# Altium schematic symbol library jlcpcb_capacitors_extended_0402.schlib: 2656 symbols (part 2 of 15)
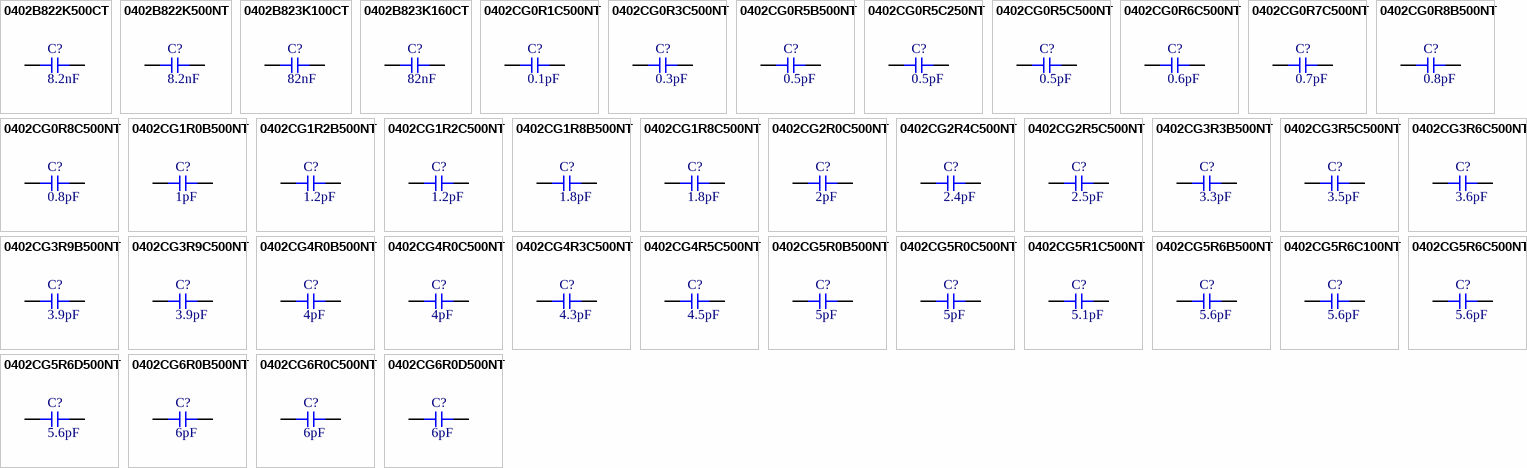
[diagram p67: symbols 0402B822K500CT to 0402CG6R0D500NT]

## 0402CG2R5C500NT
designator C?  Capacitance: 2.5pF  (hidden comment: *)
Capacitor, Ceramic (MLCC), 2.5pF, ±0.25pF, 50V, C0G, ±0.25pF, SMD 0402; Manufacturer: FH(Guangdong Fenghua Advanced Tech); Manufacturer Part Number: 0402CG2R5C500NT
footprint CAP-0402 (0402 (1005M) Capacitor)
pins: 1, 2

## 0402CG3R3B500NT
designator C?  Capacitance: 3.3pF  (hidden comment: *)
Capacitor, Ceramic (MLCC), 3.3pF, ±0.1pF, 50V, C0G, ±0.1pF, SMD 0402; Manufacturer: FH(Guangdong Fenghua Advanced Tech); Manufacturer Part Number: 0402CG3R3B500NT
footprint CAP-0402 (0402 (1005M) Capacitor)
pins: 1, 2

## 0402CG3R5C500NT
designator C?  Capacitance: 3.5pF  (hidden comment: *)
Capacitor, Ceramic (MLCC), 3.5pF, ±0.25pF, 50V, C0G, ±0.25pF, SMD 0402; Manufacturer: FH(Guangdong Fenghua Advanced Tech); Manufacturer Part Number: 0402CG3R5C500NT
footprint CAP-0402 (0402 (1005M) Capacitor)
pins: 1, 2

## 0402CG3R6C500NT
designator C?  Capacitance: 3.6pF  (hidden comment: *)
Capacitor, Ceramic (MLCC), 3.6pF, ±0.25pF, 50V, C0G, ±0.25pF, SMD 0402; Manufacturer: FH(Guangdong Fenghua Advanced Tech); Manufacturer Part Number: 0402CG3R6C500NT
footprint CAP-0402 (0402 (1005M) Capacitor)
pins: 1, 2

## 0402CG3R9B500NT
designator C?  Capacitance: 3.9pF  (hidden comment: *)
Capacitor, Ceramic (MLCC), 3.9pF, ±0.1pF, 50V, C0G, ±0.1pF, SMD 0402; Manufacturer: FH(Guangdong Fenghua Advanced Tech); Manufacturer Part Number: 0402CG3R9B500NT
footprint CAP-0402 (0402 (1005M) Capacitor)
pins: 1, 2

## 0402CG3R9C500NT
designator C?  Capacitance: 3.9pF  (hidden comment: *)
Capacitor, Ceramic (MLCC), 3.9pF, ±0.25pF, 50V, C0G, ±0.25pF, SMD 0402; Manufacturer: FH(Guangdong Fenghua Advanced Tech); Manufacturer Part Number: 0402CG3R9C500NT
footprint CAP-0402 (0402 (1005M) Capacitor)
pins: 1, 2

## 0402CG4R0B500NT
designator C?  Capacitance: 4pF  (hidden comment: *)
Capacitor, Ceramic (MLCC), 4pF, ±0.1pF, 50V, C0G, ±0.1pF, SMD 0402; Manufacturer: FH(Guangdong Fenghua Advanced Tech); Manufacturer Part Number: 0402CG4R0B500NT
footprint CAP-0402 (0402 (1005M) Capacitor)
pins: 1, 2

## 0402CG4R0C500NT
designator C?  Capacitance: 4pF  (hidden comment: *)
Capacitor, Ceramic (MLCC), 4pF, ±0.25pF, 50V, C0G, ±0.25pF, SMD 0402; Manufacturer: FH(Guangdong Fenghua Advanced Tech); Manufacturer Part Number: 0402CG4R0C500NT
footprint CAP-0402 (0402 (1005M) Capacitor)
pins: 1, 2

## 0402CG4R3C500NT
designator C?  Capacitance: 4.3pF  (hidden comment: *)
Capacitor, Ceramic (MLCC), 4.3pF, ±0.25pF, 50V, C0G, ±0.25pF, SMD 0402; Manufacturer: FH(Guangdong Fenghua Advanced Tech); Manufacturer Part Number: 0402CG4R3C500NT
footprint CAP-0402 (0402 (1005M) Capacitor)
pins: 1, 2

## 0402CG4R5C500NT
designator C?  Capacitance: 4.5pF  (hidden comment: *)
Capacitor, Ceramic (MLCC), 4.5pF, ±0.25pF, 50V, C0G, ±0.25pF, SMD 0402; Manufacturer: FH(Guangdong Fenghua Advanced Tech); Manufacturer Part Number: 0402CG4R5C500NT
footprint CAP-0402 (0402 (1005M) Capacitor)
pins: 1, 2

## 0402CG5R0B500NT
designator C?  Capacitance: 5pF  (hidden comment: *)
Capacitor, Ceramic (MLCC), 5pF, ±0.1pF, 50V, ±0.1pF, SMD 0402; Manufacturer: FH(Guangdong Fenghua Advanced Tech); Manufacturer Part Number: 0402CG5R0B500NT
footprint CAP-0402 (0402 (1005M) Capacitor)
pins: 1, 2

## 0402CG5R0C500NT
designator C?  Capacitance: 5pF  (hidden comment: *)
Capacitor, Ceramic (MLCC), 5pF, ±0.25pF, 50V, C0G, ±0.25pF, SMD 0402; Manufacturer: FH(Guangdong Fenghua Advanced Tech); Manufacturer Part Number: 0402CG5R0C500NT
footprint CAP-0402 (0402 (1005M) Capacitor)
pins: 1, 2

## 0402CG5R1C500NT
designator C?  Capacitance: 5.1pF  (hidden comment: *)
Capacitor, Ceramic (MLCC), 5.1pF, ±0.25pF, 50V, C0G, ±0.25pF, SMD 0402; Manufacturer: FH(Guangdong Fenghua Advanced Tech); Manufacturer Part Number: 0402CG5R1C500NT
footprint CAP-0402 (0402 (1005M) Capacitor)
pins: 1, 2

## 0402CG5R6B500NT
designator C?  Capacitance: 5.6pF  (hidden comment: *)
Capacitor, Ceramic (MLCC), 5.6pF, ±0.1pF, 50V, C0G, ±0.1pF, SMD 0402; Manufacturer: FH (Guangdong Fenghua Advanced Tech); Manufacturer Part Number: 0402CG5R6B500NT
footprint CAP-0402 (0402 (1005M) Capacitor)
pins: 1, 2

## 0402CG5R6C100NT
designator C?  Capacitance: 5.6pF  (hidden comment: *)
Capacitor, Ceramic (MLCC), 5.6pF, ±0.25pF, 10V, C0G, ±0.25pF, SMD 0402; Manufacturer: FH(Guangdong Fenghua Advanced Tech); Manufacturer Part Number: 0402CG5R6C100NT
footprint CAP-0402 (0402 (1005M) Capacitor)
pins: 1, 2

## 0402CG5R6C500NT
designator C?  Capacitance: 5.6pF  (hidden comment: *)
Capacitor, Ceramic (MLCC), 5.6pF, ±0.25pF, 50V, C0G, ±0.25pF, SMD 0402; Manufacturer: FH(Guangdong Fenghua Advanced Tech); Manufacturer Part Number: 0402CG5R6C500NT
footprint CAP-0402 (0402 (1005M) Capacitor)
pins: 1, 2

## 0402CG5R6D500NT
designator C?  Capacitance: 5.6pF  (hidden comment: *)
Capacitor, Ceramic (MLCC), 5.6pF, ±0.5pF, 50V, C0G, ±0.5pF, SMD 0402; Manufacturer: FH(Guangdong Fenghua Advanced Tech); Manufacturer Part Number: 0402CG5R6D500NT
footprint CAP-0402 (0402 (1005M) Capacitor)
pins: 1, 2

## 0402CG6R0B500NT
designator C?  Capacitance: 6pF  (hidden comment: *)
Capacitor, Ceramic (MLCC), 6pF, ±0.1pF, 50V, ±0.1pF, SMD 0402; Manufacturer: FH(Guangdong Fenghua Advanced Tech); Manufacturer Part Number: 0402CG6R0B500NT
footprint CAP-0402 (0402 (1005M) Capacitor)
pins: 1, 2

## 0402CG6R0C500NT
designator C?  Capacitance: 6pF  (hidden comment: *)
Capacitor, Ceramic (MLCC), 6pF, ±0.25pF, 50V, C0G, ±0.25pF, SMD 0402; Manufacturer: FH(Guangdong Fenghua Advanced Tech); Manufacturer Part Number: 0402CG6R0C500NT
footprint CAP-0402 (0402 (1005M) Capacitor)
pins: 1, 2

## 0402CG6R0D500NT
designator C?  Capacitance: 6pF  (hidden comment: *)
Capacitor, Ceramic (MLCC), 6pF, ±0.5pF, 50V, C0G, ±0.5pF, SMD 0402; Manufacturer: FH(Guangdong Fenghua Advanced Tech); Manufacturer Part Number: 0402CG6R0D500NT
footprint CAP-0402 (0402 (1005M) Capacitor)
pins: 1, 2

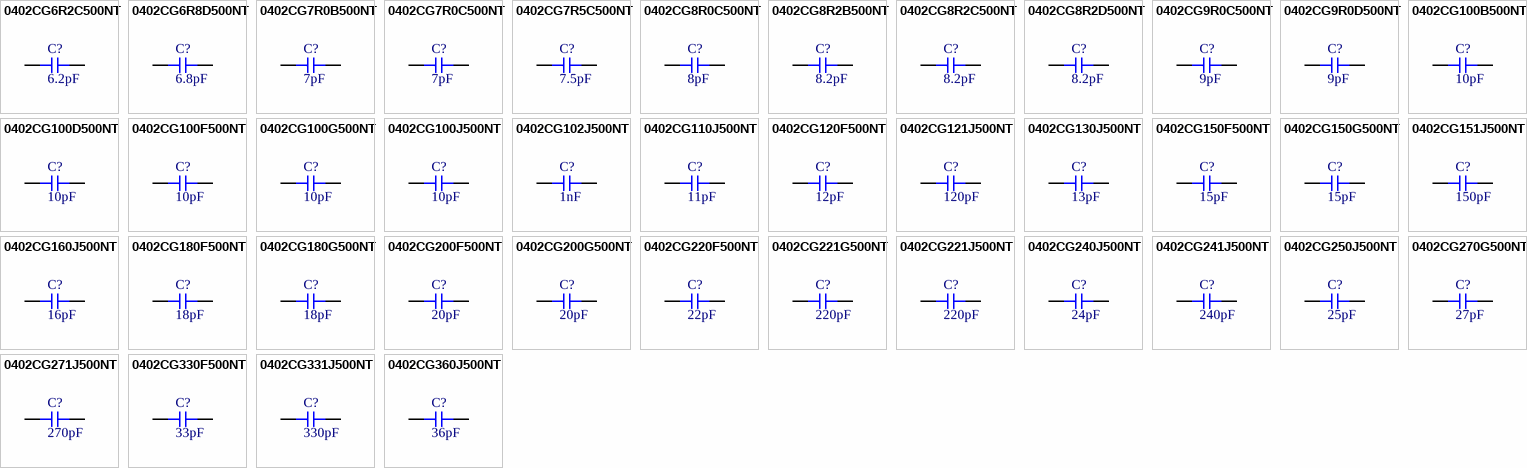
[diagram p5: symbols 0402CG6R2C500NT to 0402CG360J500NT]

## 0402CG6R2C500NT
designator C?  Capacitance: 6.2pF  (hidden comment: *)
Capacitor, Ceramic (MLCC), 6.2pF, ±0.25pF, 50V, C0G, ±0.25pF, SMD 0402; Manufacturer: FH(Guangdong Fenghua Advanced Tech); Manufacturer Part Number: 0402CG6R2C500NT
footprint CAP-0402 (0402 (1005M) Capacitor)
pins: 1, 2

## 0402CG6R8D500NT
designator C?  Capacitance: 6.8pF  (hidden comment: *)
Capacitor, Ceramic (MLCC), 6.8pF, ±0.5pF, 50V, C0G, ±0.5pF, SMD 0402; Manufacturer: FH(Guangdong Fenghua Advanced Tech); Manufacturer Part Number: 0402CG6R8D500NT
footprint CAP-0402 (0402 (1005M) Capacitor)
pins: 1, 2

## 0402CG7R0B500NT
designator C?  Capacitance: 7pF  (hidden comment: *)
Capacitor, Ceramic (MLCC), 7pF, ±0.1pF, 50V, C0G, ±0.1pF, SMD 0402; Manufacturer: FH(Guangdong Fenghua Advanced Tech); Manufacturer Part Number: 0402CG7R0B500NT
footprint CAP-0402 (0402 (1005M) Capacitor)
pins: 1, 2

## 0402CG7R0C500NT
designator C?  Capacitance: 7pF  (hidden comment: *)
Capacitor, Ceramic (MLCC), 7pF, ±0.25pF, 50V, C0G, ±0.25pF, SMD 0402; Manufacturer: FH(Guangdong Fenghua Advanced Tech); Manufacturer Part Number: 0402CG7R0C500NT
footprint CAP-0402 (0402 (1005M) Capacitor)
pins: 1, 2

## 0402CG7R5C500NT
designator C?  Capacitance: 7.5pF  (hidden comment: *)
Capacitor, Ceramic (MLCC), 7.5pF, ±0.25pF, 50V, C0G, ±0.25pF, SMD 0402; Manufacturer: FH(Guangdong Fenghua Advanced Tech); Manufacturer Part Number: 0402CG7R5C500NT
footprint CAP-0402 (0402 (1005M) Capacitor)
pins: 1, 2

## 0402CG8R0C500NT
designator C?  Capacitance: 8pF  (hidden comment: *)
Capacitor, Ceramic (MLCC), 8pF, ±0.25pF, 50V, C0G, ±0.25pF, SMD 0402; Manufacturer: FH(Guangdong Fenghua Advanced Tech); Manufacturer Part Number: 0402CG8R0C500NT
footprint CAP-0402 (0402 (1005M) Capacitor)
pins: 1, 2

## 0402CG8R2B500NT
designator C?  Capacitance: 8.2pF  (hidden comment: *)
Capacitor, Ceramic (MLCC), 8.2pF, ±0.1pF, 50V, C0G, ±0.1pF, SMD 0402; Manufacturer: FH(Guangdong Fenghua Advanced Tech); Manufacturer Part Number: 0402CG8R2B500NT
footprint CAP-0402 (0402 (1005M) Capacitor)
pins: 1, 2

## 0402CG8R2C500NT
designator C?  Capacitance: 8.2pF  (hidden comment: *)
Capacitor, Ceramic (MLCC), 8.2pF, ±0.25pF, 50V, C0G, ±0.25pF, SMD 0402; Manufacturer: FH(Guangdong Fenghua Advanced Tech); Manufacturer Part Number: 0402CG8R2C500NT
footprint CAP-0402 (0402 (1005M) Capacitor)
pins: 1, 2

## 0402CG8R2D500NT
designator C?  Capacitance: 8.2pF  (hidden comment: *)
Capacitor, Ceramic (MLCC), 8.2pF, ±0.5pF, 50V, C0G, ±0.5pF, SMD 0402; Manufacturer: FH(Guangdong Fenghua Advanced Tech); Manufacturer Part Number: 0402CG8R2D500NT
footprint CAP-0402 (0402 (1005M) Capacitor)
pins: 1, 2

## 0402CG9R0C500NT
designator C?  Capacitance: 9pF  (hidden comment: *)
Capacitor, Ceramic (MLCC), 9pF, ±0.25pF, 50V, C0G, ±0.25pF, SMD 0402; Manufacturer: FH(Guangdong Fenghua Advanced Tech); Manufacturer Part Number: 0402CG9R0C500NT
footprint CAP-0402 (0402 (1005M) Capacitor)
pins: 1, 2

## 0402CG9R0D500NT
designator C?  Capacitance: 9pF  (hidden comment: *)
Capacitor, Ceramic (MLCC), 9pF, ±0.5pF, 50V, C0G, ±0.5pF, SMD 0402; Manufacturer: FH(Guangdong Fenghua Advanced Tech); Manufacturer Part Number: 0402CG9R0D500NT
footprint CAP-0402 (0402 (1005M) Capacitor)
pins: 1, 2

## 0402CG100B500NT
designator C?  Capacitance: 10pF  (hidden comment: *)
Capacitor, Ceramic (MLCC), 10pF, ±0.1pF, 50V, C0G, ±0.1pF, SMD 0402; Manufacturer: FH(Guangdong Fenghua Advanced Tech); Manufacturer Part Number: 0402CG100B500NT
footprint CAP-0402 (0402 (1005M) Capacitor)
pins: 1, 2

## 0402CG100D500NT
designator C?  Capacitance: 10pF  (hidden comment: *)
Capacitor, Ceramic (MLCC), 10pF, ±0.5pF, 50V, C0G, ±0.5pF, SMD 0402; Manufacturer: FH(Guangdong Fenghua Advanced Tech); Manufacturer Part Number: 0402CG100D500NT
footprint CAP-0402 (0402 (1005M) Capacitor)
pins: 1, 2

## 0402CG100F500NT
designator C?  Capacitance: 10pF  (hidden comment: *)
Capacitor, Ceramic (MLCC), 10pF, ±1%, 50V, C0G, ±1%, SMD 0402; Manufacturer: FH(Guangdong Fenghua Advanced Tech); Manufacturer Part Number: 0402CG100F500NT
footprint CAP-0402 (0402 (1005M) Capacitor)
pins: 1, 2

## 0402CG100G500NT
designator C?  Capacitance: 10pF  (hidden comment: *)
Capacitor, Ceramic (MLCC), 10pF, ±2%, 50V, C0G, ±2%, SMD 0402; Manufacturer: FH(Guangdong Fenghua Advanced Tech); Manufacturer Part Number: 0402CG100G500NT
footprint CAP-0402 (0402 (1005M) Capacitor)
pins: 1, 2

## 0402CG100J500NT
designator C?  Capacitance: 10pF  (hidden comment: *)
Capacitor, Ceramic (MLCC), 10pF, ±5%, 50V, C0G, ±5%, SMD 0402; Manufacturer: FH(Guangdong Fenghua Advanced Tech); Manufacturer Part Number: 0402CG100J500NT
footprint CAP-0402 (0402 (1005M) Capacitor)
pins: 1, 2

## 0402CG102J500NT
designator C?  Capacitance: 1nF  (hidden comment: *)
Capacitor, Ceramic (MLCC), 1nF, ±5%, 50V, C0G, ±5%, SMD 0402; Manufacturer: FH(Guangdong Fenghua Advanced Tech); Manufacturer Part Number: 0402CG102J500NT
footprint CAP-0402 (0402 (1005M) Capacitor)
pins: 1, 2

## 0402CG110J500NT
designator C?  Capacitance: 11pF  (hidden comment: *)
Capacitor, Ceramic (MLCC), 11pF, ±5%, 50V, C0G, ±5%, SMD 0402; Manufacturer: FH(Guangdong Fenghua Advanced Tech); Manufacturer Part Number: 0402CG110J500NT
footprint CAP-0402 (0402 (1005M) Capacitor)
pins: 1, 2

## 0402CG120F500NT
designator C?  Capacitance: 12pF  (hidden comment: *)
Capacitor, Ceramic (MLCC), 12pF, ±1%, 50V, C0G, ±1%, SMD 0402; Manufacturer: FH(Guangdong Fenghua Advanced Tech); Manufacturer Part Number: 0402CG120F500NT
footprint CAP-0402 (0402 (1005M) Capacitor)
pins: 1, 2

## 0402CG121J500NT
designator C?  Capacitance: 120pF  (hidden comment: *)
Capacitor, Ceramic (MLCC), 120pF, ±5%, 50V, C0G, ±5%, SMD 0402; Manufacturer: FH(Guangdong Fenghua Advanced Tech); Manufacturer Part Number: 0402CG121J500NT
footprint CAP-0402 (0402 (1005M) Capacitor)
pins: 1, 2

## 0402CG130J500NT
designator C?  Capacitance: 13pF  (hidden comment: *)
Capacitor, Ceramic (MLCC), 13pF, ±5%, 50V, C0G, ±5%, SMD 0402; Manufacturer: FH(Guangdong Fenghua Advanced Tech); Manufacturer Part Number: 0402CG130J500NT
footprint CAP-0402 (0402 (1005M) Capacitor)
pins: 1, 2

## 0402CG150F500NT
designator C?  Capacitance: 15pF  (hidden comment: *)
Capacitor, Ceramic (MLCC), 15pF, ±1%, 50V, C0G, ±1%, SMD 0402; Manufacturer: FH(Guangdong Fenghua Advanced Tech); Manufacturer Part Number: 0402CG150F500NT
footprint CAP-0402 (0402 (1005M) Capacitor)
pins: 1, 2

## 0402CG150G500NT
designator C?  Capacitance: 15pF  (hidden comment: *)
Capacitor, Ceramic (MLCC), 15pF, ±2%, 50V, C0G, ±2%, SMD 0402; Manufacturer: FH(Guangdong Fenghua Advanced Tech); Manufacturer Part Number: 0402CG150G500NT
footprint CAP-0402 (0402 (1005M) Capacitor)
pins: 1, 2

## 0402CG151J500NT
designator C?  Capacitance: 150pF  (hidden comment: *)
Capacitor, Ceramic (MLCC), 150pF, ±5%, 50V, C0G, ±5%, SMD 0402; Manufacturer: FH(Guangdong Fenghua Advanced Tech); Manufacturer Part Number: 0402CG151J500NT
footprint CAP-0402 (0402 (1005M) Capacitor)
pins: 1, 2

## 0402CG160J500NT
designator C?  Capacitance: 16pF  (hidden comment: *)
Capacitor, Ceramic (MLCC), 16pF, ±5%, 50V, C0G, ±5%, SMD 0402; Manufacturer: FH(Guangdong Fenghua Advanced Tech); Manufacturer Part Number: 0402CG160J500NT
footprint CAP-0402 (0402 (1005M) Capacitor)
pins: 1, 2

## 0402CG180F500NT
designator C?  Capacitance: 18pF  (hidden comment: *)
Capacitor, Ceramic (MLCC), 18pF, ±1%, 50V, C0G, ±1%, SMD 0402; Manufacturer: FH(Guangdong Fenghua Advanced Tech); Manufacturer Part Number: 0402CG180F500NT
footprint CAP-0402 (0402 (1005M) Capacitor)
pins: 1, 2

## 0402CG180G500NT
designator C?  Capacitance: 18pF  (hidden comment: *)
Capacitor, Ceramic (MLCC), 18pF, ±2%, 50V, C0G, ±2%, SMD 0402; Manufacturer: FH(Guangdong Fenghua Advanced Tech); Manufacturer Part Number: 0402CG180G500NT
footprint CAP-0402 (0402 (1005M) Capacitor)
pins: 1, 2

## 0402CG200F500NT
designator C?  Capacitance: 20pF  (hidden comment: *)
Capacitor, Ceramic (MLCC), 20pF, ±1%, 50V, C0G, ±1%, SMD 0402; Manufacturer: FH(Guangdong Fenghua Advanced Tech); Manufacturer Part Number: 0402CG200F500NT
footprint CAP-0402 (0402 (1005M) Capacitor)
pins: 1, 2

## 0402CG200G500NT
designator C?  Capacitance: 20pF  (hidden comment: *)
Capacitor, Ceramic (MLCC), 20pF, ±2%, 50V, C0G, ±2%, SMD 0402; Manufacturer: FH(Guangdong Fenghua Advanced Tech); Manufacturer Part Number: 0402CG200G500NT
footprint CAP-0402 (0402 (1005M) Capacitor)
pins: 1, 2

## 0402CG220F500NT
designator C?  Capacitance: 22pF  (hidden comment: *)
Capacitor, Ceramic (MLCC), 22pF, ±1%, 50V, C0G, ±1%, SMD 0402; Manufacturer: FH(Guangdong Fenghua Advanced Tech); Manufacturer Part Number: 0402CG220F500NT
footprint CAP-0402 (0402 (1005M) Capacitor)
pins: 1, 2

## 0402CG221G500NT
designator C?  Capacitance: 220pF  (hidden comment: *)
Capacitor, Ceramic (MLCC), 220pF, ±2%, 50V, C0G, ±2%, SMD 0402; Manufacturer: FH(Guangdong Fenghua Advanced Tech); Manufacturer Part Number: 0402CG221G500NT
footprint CAP-0402 (0402 (1005M) Capacitor)
pins: 1, 2

## 0402CG221J500NT
designator C?  Capacitance: 220pF  (hidden comment: *)
Capacitor, Ceramic (MLCC), 220pF, ±5%, 50V, C0G, ±5%, SMD 0402; Manufacturer: FH(Guangdong Fenghua Advanced Tech); Manufacturer Part Number: 0402CG221J500NT
footprint CAP-0402 (0402 (1005M) Capacitor)
pins: 1, 2

## 0402CG240J500NT
designator C?  Capacitance: 24pF  (hidden comment: *)
Capacitor, Ceramic (MLCC), 24pF, ±5%, 50V, C0G, ±5%, SMD 0402; Manufacturer: FH(Guangdong Fenghua Advanced Tech); Manufacturer Part Number: 0402CG240J500NT
footprint CAP-0402 (0402 (1005M) Capacitor)
pins: 1, 2

## 0402CG241J500NT
designator C?  Capacitance: 240pF  (hidden comment: *)
Capacitor, Ceramic (MLCC), 240pF, ±5%, 50V, ±5%, SMD 0402; Manufacturer: FH(Guangdong Fenghua Advanced Tech); Manufacturer Part Number: 0402CG241J500NT
footprint CAP-0402 (0402 (1005M) Capacitor)
pins: 1, 2

## 0402CG250J500NT
designator C?  Capacitance: 25pF  (hidden comment: *)
Capacitor, Ceramic (MLCC), 25pF, ±5%, 50V, C0G, ±5%, SMD 0402; Manufacturer: FH(Guangdong Fenghua Advanced Tech); Manufacturer Part Number: 0402CG250J500NT
footprint CAP-0402 (0402 (1005M) Capacitor)
pins: 1, 2

## 0402CG270G500NT
designator C?  Capacitance: 27pF  (hidden comment: *)
Capacitor, Ceramic (MLCC), 27pF, ±2%, 50V, C0G, ±2%, SMD 0402; Manufacturer: FH(Guangdong Fenghua Advanced Tech); Manufacturer Part Number: 0402CG270G500NT
footprint CAP-0402 (0402 (1005M) Capacitor)
pins: 1, 2

## 0402CG271J500NT
designator C?  Capacitance: 270pF  (hidden comment: *)
Capacitor, Ceramic (MLCC), 270pF, ±5%, 50V, C0G, ±5%, SMD 0402; Manufacturer: FH(Guangdong Fenghua Advanced Tech); Manufacturer Part Number: 0402CG271J500NT
footprint CAP-0402 (0402 (1005M) Capacitor)
pins: 1, 2

## 0402CG330F500NT
designator C?  Capacitance: 33pF  (hidden comment: *)
Capacitor, Ceramic (MLCC), 33pF, ±1%, 50V, C0G, ±1%, SMD 0402; Manufacturer: FH(Guangdong Fenghua Advanced Tech); Manufacturer Part Number: 0402CG330F500NT
footprint CAP-0402 (0402 (1005M) Capacitor)
pins: 1, 2

## 0402CG331J500NT
designator C?  Capacitance: 330pF  (hidden comment: *)
Capacitor, Ceramic (MLCC), 330pF, ±5%, 50V, C0G, ±5%, SMD 0402; Manufacturer: FH(Guangdong Fenghua Advanced Tech); Manufacturer Part Number: 0402CG331J500NT
footprint CAP-0402 (0402 (1005M) Capacitor)
pins: 1, 2

## 0402CG360J500NT
designator C?  Capacitance: 36pF  (hidden comment: *)
Capacitor, Ceramic (MLCC), 36pF, ±5%, 50V, C0G, ±5%, SMD 0402; Manufacturer: FH(Guangdong Fenghua Advanced Tech); Manufacturer Part Number: 0402CG360J500NT
footprint CAP-0402 (0402 (1005M) Capacitor)
pins: 1, 2

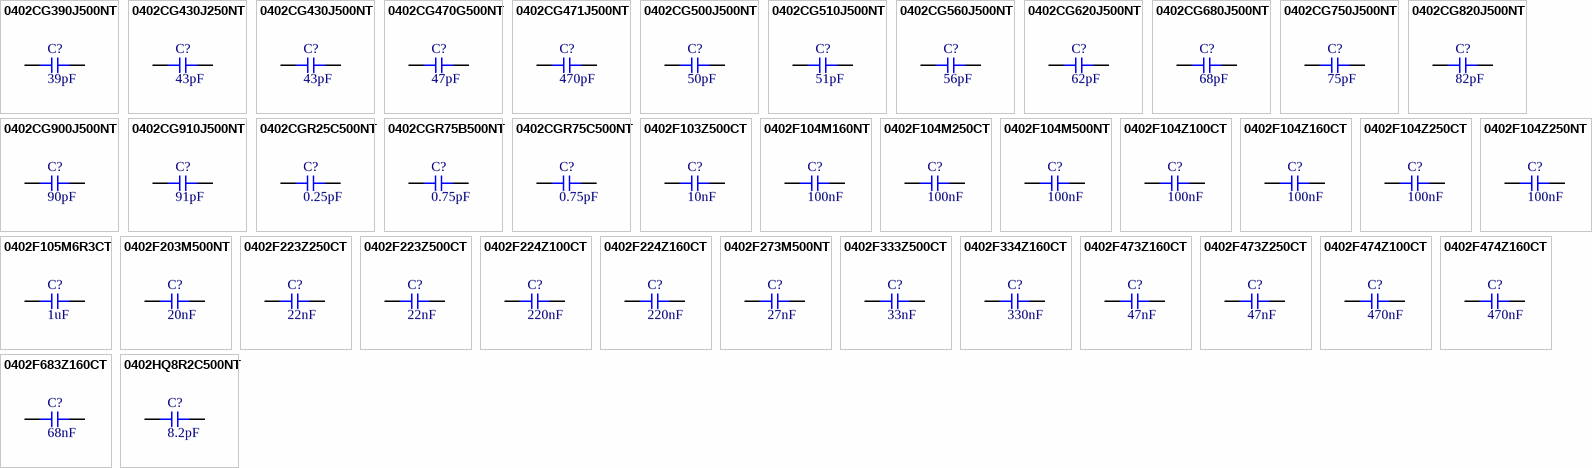
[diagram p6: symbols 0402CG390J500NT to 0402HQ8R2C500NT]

## 0402CG390J500NT
designator C?  Capacitance: 39pF  (hidden comment: *)
Capacitor, Ceramic (MLCC), 39pF, ±5%, 50V, C0G, ±5%, SMD 0402; Manufacturer: FH(Guangdong Fenghua Advanced Tech); Manufacturer Part Number: 0402CG390J500NT
footprint CAP-0402 (0402 (1005M) Capacitor)
pins: 1, 2

## 0402CG430J250NT
designator C?  Capacitance: 43pF  (hidden comment: *)
Capacitor, Ceramic (MLCC), 43pF, ±5%, 25V, C0G, ±5%, SMD 0402; Manufacturer: FH(Guangdong Fenghua Advanced Tech); Manufacturer Part Number: 0402CG430J250NT
footprint CAP-0402 (0402 (1005M) Capacitor)
pins: 1, 2

## 0402CG430J500NT
designator C?  Capacitance: 43pF  (hidden comment: *)
Capacitor, Ceramic (MLCC), 43pF, ±5%, 50V, C0G, ±5%, SMD 0402; Manufacturer: FH(Guangdong Fenghua Advanced Tech); Manufacturer Part Number: 0402CG430J500NT
footprint CAP-0402 (0402 (1005M) Capacitor)
pins: 1, 2

## 0402CG470G500NT
designator C?  Capacitance: 47pF  (hidden comment: *)
Capacitor, Ceramic (MLCC), 47pF, ±2%, 50V, C0G, ±2%, SMD 0402; Manufacturer: FH(Guangdong Fenghua Advanced Tech); Manufacturer Part Number: 0402CG470G500NT
footprint CAP-0402 (0402 (1005M) Capacitor)
pins: 1, 2

## 0402CG471J500NT
designator C?  Capacitance: 470pF  (hidden comment: *)
Capacitor, Ceramic (MLCC), 470pF, ±5%, 50V, C0G, ±5%, SMD 0402; Manufacturer: FH(Guangdong Fenghua Advanced Tech); Manufacturer Part Number: 0402CG471J500NT
footprint CAP-0402 (0402 (1005M) Capacitor)
pins: 1, 2

## 0402CG500J500NT
designator C?  Capacitance: 50pF  (hidden comment: *)
Capacitor, Ceramic (MLCC), 50pF, ±5%, 50V, C0G, ±5%, SMD 0402; Manufacturer: FH(Guangdong Fenghua Advanced Tech); Manufacturer Part Number: 0402CG500J500NT
footprint CAP-0402 (0402 (1005M) Capacitor)
pins: 1, 2

## 0402CG510J500NT
designator C?  Capacitance: 51pF  (hidden comment: *)
Capacitor, Ceramic (MLCC), 51pF, ±5%, 50V, C0G, ±5%, SMD 0402; Manufacturer: FH(Guangdong Fenghua Advanced Tech); Manufacturer Part Number: 0402CG510J500NT
footprint CAP-0402 (0402 (1005M) Capacitor)
pins: 1, 2

## 0402CG560J500NT
designator C?  Capacitance: 56pF  (hidden comment: *)
Capacitor, Ceramic (MLCC), 56pF, ±5%, 50V, C0G, ±5%, SMD 0402; Manufacturer: FH(Guangdong Fenghua Advanced Tech); Manufacturer Part Number: 0402CG560J500NT
footprint CAP-0402 (0402 (1005M) Capacitor)
pins: 1, 2

## 0402CG620J500NT
designator C?  Capacitance: 62pF  (hidden comment: *)
Capacitor, Ceramic (MLCC), 62pF, ±5%, 50V, C0G, ±5%, SMD 0402; Manufacturer: FH(Guangdong Fenghua Advanced Tech); Manufacturer Part Number: 0402CG620J500NT
footprint CAP-0402 (0402 (1005M) Capacitor)
pins: 1, 2

## 0402CG680J500NT
designator C?  Capacitance: 68pF  (hidden comment: *)
Capacitor, Ceramic (MLCC), 68pF, ±5%, 50V, C0G, ±5%, SMD 0402; Manufacturer: FH(Guangdong Fenghua Advanced Tech); Manufacturer Part Number: 0402CG680J500NT
footprint CAP-0402 (0402 (1005M) Capacitor)
pins: 1, 2

## 0402CG750J500NT
designator C?  Capacitance: 75pF  (hidden comment: *)
Capacitor, Ceramic (MLCC), 75pF, ±5%, 50V, C0G, ±5%, SMD 0402; Manufacturer: FH(Guangdong Fenghua Advanced Tech); Manufacturer Part Number: 0402CG750J500NT
footprint CAP-0402 (0402 (1005M) Capacitor)
pins: 1, 2

## 0402CG820J500NT
designator C?  Capacitance: 82pF  (hidden comment: *)
Capacitor, Ceramic (MLCC), 82pF, ±5%, 50V, C0G, ±5%, SMD 0402; Manufacturer: FH(Guangdong Fenghua Advanced Tech); Manufacturer Part Number: 0402CG820J500NT
footprint CAP-0402 (0402 (1005M) Capacitor)
pins: 1, 2

## 0402CG900J500NT
designator C?  Capacitance: 90pF  (hidden comment: *)
Capacitor, Ceramic (MLCC), 90pF, ±5%, 50V, C0G, ±5%, SMD 0402; Manufacturer: FH(Guangdong Fenghua Advanced Tech); Manufacturer Part Number: 0402CG900J500NT
footprint CAP-0402 (0402 (1005M) Capacitor)
pins: 1, 2

## 0402CG910J500NT
designator C?  Capacitance: 91pF  (hidden comment: *)
Capacitor, Ceramic (MLCC), 91pF, ±5%, 50V, C0G, ±5%, SMD 0402; Manufacturer: FH(Guangdong Fenghua Advanced Tech); Manufacturer Part Number: 0402CG910J500NT
footprint CAP-0402 (0402 (1005M) Capacitor)
pins: 1, 2

## 0402CGR25C500NT
designator C?  Capacitance: 0.25pF  (hidden comment: *)
Capacitor, Ceramic (MLCC), 0.25pF, ±0.25pF, 50V, C0G, ±0.25pF, SMD 0402; Manufacturer: FH(Guangdong Fenghua Advanced Tech); Manufacturer Part Number: 0402CGR25C500NT
footprint CAP-0402 (0402 (1005M) Capacitor)
pins: 1, 2

## 0402CGR75B500NT
designator C?  Capacitance: 0.75pF  (hidden comment: *)
Capacitor, Ceramic (MLCC), 0.75pF, ±0.1pF, 50V, C0G, ±0.1pF, SMD 0402; Manufacturer: FH(Guangdong Fenghua Advanced Tech); Manufacturer Part Number: 0402CGR75B500NT
footprint CAP-0402 (0402 (1005M) Capacitor)
pins: 1, 2

## 0402CGR75C500NT
designator C?  Capacitance: 0.75pF  (hidden comment: *)
Capacitor, Ceramic (MLCC), 0.75pF, ±0.25pF, 50V, C0G, ±0.25pF, SMD 0402; Manufacturer: FH(Guangdong Fenghua Advanced Tech); Manufacturer Part Number: 0402CGR75C500NT
footprint CAP-0402 (0402 (1005M) Capacitor)
pins: 1, 2

## 0402F103Z500CT
designator C?  Capacitance: 10nF  (hidden comment: *)
Capacitor, Ceramic (MLCC), 10nF, 50V, Y5V, SMD 0402; Manufacturer: Walsin Tech Corp; Manufacturer Part Number: 0402F103Z500CT; Temperature Rating: -20%~+80%
footprint CAP-0402 (0402 (1005M) Capacitor)
pins: 1, 2

## 0402F104M160NT
designator C?  Capacitance: 100nF  (hidden comment: *)
Capacitor, Ceramic (MLCC), 100nF, ±20%, 16V, Y5V, ±20%, SMD 0402; Manufacturer: FH(Guangdong Fenghua Advanced Tech); Manufacturer Part Number: 0402F104M160NT
footprint CAP-0402 (0402 (1005M) Capacitor)
pins: 1, 2

## 0402F104M250CT
designator C?  Capacitance: 100nF  (hidden comment: *)
Capacitor, Ceramic (MLCC), 100nF, ±20%, 25V, Y5V, ±20%, SMD 0402; Manufacturer: Walsin Tech Corp; Manufacturer Part Number: 0402F104M250CT
footprint CAP-0402 (0402 (1005M) Capacitor)
pins: 1, 2

## 0402F104M500NT
designator C?  Capacitance: 100nF  (hidden comment: *)
Capacitor, Ceramic (MLCC), 100nF, ±20%, 50V, Y5V, ±20%, SMD 0402; Manufacturer: FH(Guangdong Fenghua Advanced Tech); Manufacturer Part Number: 0402F104M500NT
footprint CAP-0402 (0402 (1005M) Capacitor)
pins: 1, 2

## 0402F104Z100CT
designator C?  Capacitance: 100nF  (hidden comment: *)
Capacitor, Ceramic (MLCC), 100nF, 10V, Y5V, SMD 0402; Manufacturer: Walsin Tech Corp; Manufacturer Part Number: 0402F104Z100CT; Temperature Rating: -20%~+80%
footprint CAP-0402 (0402 (1005M) Capacitor)
pins: 1, 2

## 0402F104Z160CT
designator C?  Capacitance: 100nF  (hidden comment: *)
Capacitor, Ceramic (MLCC), 100nF, 16V, Y5V, SMD 0402; Manufacturer: Walsin Tech Corp; Manufacturer Part Number: 0402F104Z160CT; Temperature Rating: -20%~+80%
footprint CAP-0402 (0402 (1005M) Capacitor)
pins: 1, 2

## 0402F104Z250CT
designator C?  Capacitance: 100nF  (hidden comment: *)
Capacitor, Ceramic (MLCC), 100nF, 25V, Y5V, SMD 0402; Manufacturer: Walsin Tech Corp; Manufacturer Part Number: 0402F104Z250CT; Temperature Rating: -20%~+80%
footprint CAP-0402 (0402 (1005M) Capacitor)
pins: 1, 2

## 0402F104Z250NT
designator C?  Capacitance: 100nF  (hidden comment: *)
Capacitor, Ceramic (MLCC), 100nF, 25V, Y5V, SMD 0402; Manufacturer: FH(Guangdong Fenghua Advanced Tech); Manufacturer Part Number: 0402F104Z250NT; Temperature Rating: -20%~+80%
footprint CAP-0402 (0402 (1005M) Capacitor)
pins: 1, 2

## 0402F105M6R3CT
designator C?  Capacitance: 1uF  (hidden comment: *)
Capacitor, Ceramic (MLCC), 1uF, ±20%, 6.3V, Y5V, ±20%, SMD 0402; Manufacturer: Walsin Tech Corp; Manufacturer Part Number: 0402F105M6R3CT
footprint CAP-0402 (0402 (1005M) Capacitor)
pins: 1, 2

## 0402F203M500NT
designator C?  Capacitance: 20nF  (hidden comment: *)
Capacitor, Ceramic (MLCC), 20nF, ±20%, 50V, Y5V, ±20%, SMD 0402; Manufacturer: FH(Guangdong Fenghua Advanced Tech); Manufacturer Part Number: 0402F203M500NT
footprint CAP-0402 (0402 (1005M) Capacitor)
pins: 1, 2

## 0402F223Z250CT
designator C?  Capacitance: 22nF  (hidden comment: *)
Capacitor, Ceramic (MLCC), 22nF, 25V, Y5V, SMD 0402; Manufacturer: Walsin Tech Corp; Manufacturer Part Number: 0402F223Z250CT; Temperature Rating: -20%~+80%
footprint CAP-0402 (0402 (1005M) Capacitor)
pins: 1, 2

## 0402F223Z500CT
designator C?  Capacitance: 22nF  (hidden comment: *)
Capacitor, Ceramic (MLCC), 22nF, 50V, Y5V, SMD 0402; Manufacturer: Walsin Tech Corp; Manufacturer Part Number: 0402F223Z500CT; Temperature Rating: -20%~+80%
footprint CAP-0402 (0402 (1005M) Capacitor)
pins: 1, 2

## 0402F224Z100CT
designator C?  Capacitance: 220nF  (hidden comment: *)
Capacitor, Ceramic (MLCC), 220nF, 10V, Y5V, SMD 0402; Manufacturer: Walsin Tech Corp; Manufacturer Part Number: 0402F224Z100CT; Temperature Rating: -20%~+80%
footprint CAP-0402 (0402 (1005M) Capacitor)
pins: 1, 2

## 0402F224Z160CT
designator C?  Capacitance: 220nF  (hidden comment: *)
Capacitor, Ceramic (MLCC), 220nF, 16V, Y5V, SMD 0402; Manufacturer: Walsin Tech Corp; Manufacturer Part Number: 0402F224Z160CT; Temperature Rating: -20%~+80%
footprint CAP-0402 (0402 (1005M) Capacitor)
pins: 1, 2

## 0402F273M500NT
designator C?  Capacitance: 27nF  (hidden comment: *)
Capacitor, Ceramic (MLCC), 27nF, ±20%, 50V, Y5V, ±20%, SMD 0402; Manufacturer: FH(Guangdong Fenghua Advanced Tech); Manufacturer Part Number: 0402F273M500NT
footprint CAP-0402 (0402 (1005M) Capacitor)
pins: 1, 2

## 0402F333Z500CT
designator C?  Capacitance: 33nF  (hidden comment: *)
Capacitor, Ceramic (MLCC), 33nF, 50V, Y5V, SMD 0402; Manufacturer: Walsin Tech Corp; Manufacturer Part Number: 0402F333Z500CT; Temperature Rating: -20%~+80%
footprint CAP-0402 (0402 (1005M) Capacitor)
pins: 1, 2

## 0402F334Z160CT
designator C?  Capacitance: 330nF  (hidden comment: *)
Capacitor, Ceramic (MLCC), 330nF, 16V, Y5V, SMD 0402; Manufacturer: Walsin Tech Corp; Manufacturer Part Number: 0402F334Z160CT; Temperature Rating: -20%~+80%
footprint CAP-0402 (0402 (1005M) Capacitor)
pins: 1, 2

## 0402F473Z160CT
designator C?  Capacitance: 47nF  (hidden comment: *)
Capacitor, Ceramic (MLCC), 47nF, 16V, Y5V, SMD 0402; Manufacturer: Walsin Tech Corp; Manufacturer Part Number: 0402F473Z160CT; Temperature Rating: -20%~+80%
footprint CAP-0402 (0402 (1005M) Capacitor)
pins: 1, 2

## 0402F473Z250CT
designator C?  Capacitance: 47nF  (hidden comment: *)
Capacitor, Ceramic (MLCC), 47nF, 25V, Y5V, SMD 0402; Manufacturer: Walsin Tech Corp; Manufacturer Part Number: 0402F473Z250CT; Temperature Rating: -20%~+80%
footprint CAP-0402 (0402 (1005M) Capacitor)
pins: 1, 2

## 0402F474Z100CT
designator C?  Capacitance: 470nF  (hidden comment: *)
Capacitor, Ceramic (MLCC), 470nF, 10V, Y5V, SMD 0402; Manufacturer: Walsin Tech Corp; Manufacturer Part Number: 0402F474Z100CT; Temperature Rating: -20%~+80%
footprint CAP-0402 (0402 (1005M) Capacitor)
pins: 1, 2

## 0402F474Z160CT
designator C?  Capacitance: 470nF  (hidden comment: *)
Capacitor, Ceramic (MLCC), 470nF, 16V, Y5V, SMD 0402; Manufacturer: Walsin Tech Corp; Manufacturer Part Number: 0402F474Z160CT; Temperature Rating: -20%~+80%
footprint CAP-0402 (0402 (1005M) Capacitor)
pins: 1, 2

## 0402F683Z160CT
designator C?  Capacitance: 68nF  (hidden comment: *)
Capacitor, Ceramic (MLCC), 68nF, 16V, Y5V, SMD 0402; Manufacturer: Walsin Tech Corp; Manufacturer Part Number: 0402F683Z160CT; Temperature Rating: -20%~+80%
footprint CAP-0402 (0402 (1005M) Capacitor)
pins: 1, 2

## 0402HQ8R2C500NT
designator C?  Capacitance: 8.2pF  (hidden comment: *)
Capacitor, Ceramic (MLCC), 8.2pF, ±0.25pF, 50V, C0G, ±0.25pF, SMD 0402; Manufacturer: FH(Guangdong Fenghua Advanced Tech); Manufacturer Part Number: 0402HQ8R2C500NT
footprint CAP-0402 (0402 (1005M) Capacitor)
pins: 1, 2

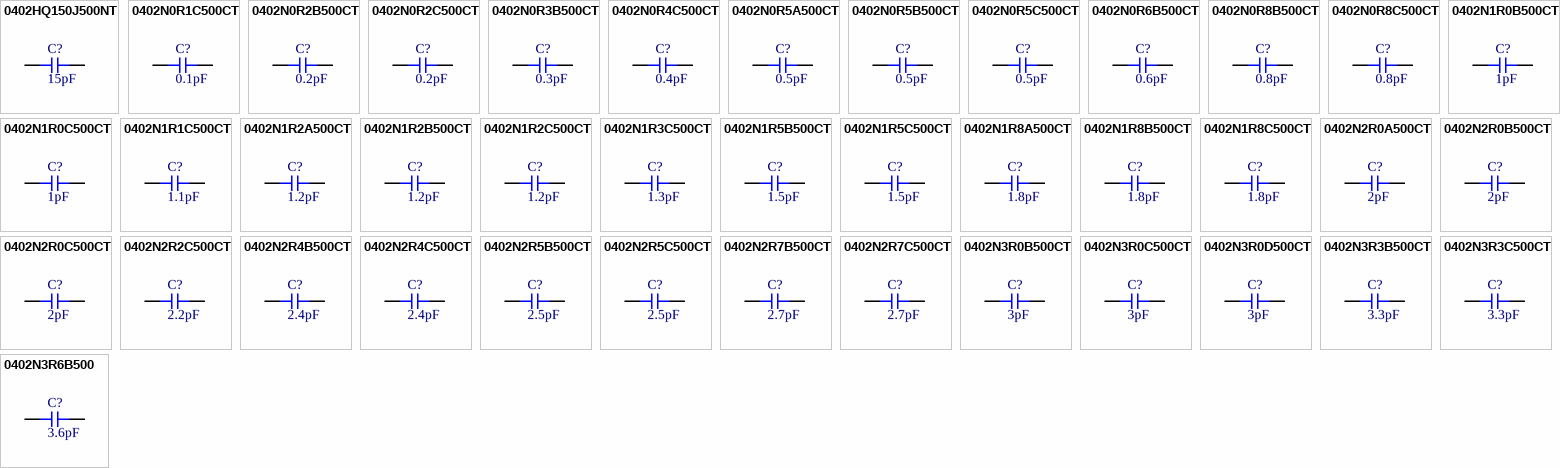
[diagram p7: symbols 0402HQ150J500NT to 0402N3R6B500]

## 0402HQ150J500NT
designator C?  Capacitance: 15pF  (hidden comment: *)
Capacitor, Ceramic (MLCC), 15pF, ±5%, 50V, C0G, ±5%, SMD 0402; Manufacturer: FH(Guangdong Fenghua Advanced Tech); Manufacturer Part Number: 0402HQ150J500NT
footprint CAP-0402 (0402 (1005M) Capacitor)
pins: 1, 2

## 0402N0R1C500CT
designator C?  Capacitance: 0.1pF  (hidden comment: *)
Capacitor, Ceramic (MLCC), 0.1pF, ±0.25pF, 50V, NP0, ±0.25pF, SMD 0402; Manufacturer: Walsin Tech Corp; Manufacturer Part Number: 0402N0R1C500CT
footprint CAP-0402 (0402 (1005M) Capacitor)
pins: 1, 2

## 0402N0R2B500CT
designator C?  Capacitance: 0.2pF  (hidden comment: *)
Capacitor, Ceramic (MLCC), 0.2pF, ±0.1pF, 50V, NP0, ±0.1pF, SMD 0402; Manufacturer: Walsin Tech Corp; Manufacturer Part Number: 0402N0R2B500CT
footprint CAP-0402 (0402 (1005M) Capacitor)
pins: 1, 2

## 0402N0R2C500CT
designator C?  Capacitance: 0.2pF  (hidden comment: *)
Capacitor, Ceramic (MLCC), 0.2pF, ±0.25pF, 50V, NP0, ±0.25pF, SMD 0402; Manufacturer: Walsin Tech Corp; Manufacturer Part Number: 0402N0R2C500CT
footprint CAP-0402 (0402 (1005M) Capacitor)
pins: 1, 2

## 0402N0R3B500CT
designator C?  Capacitance: 0.3pF  (hidden comment: *)
Capacitor, Ceramic (MLCC), 0.3pF, ±0.1pF, 50V, NP0, ±0.1pF, SMD 0402; Manufacturer: Walsin Tech Corp; Manufacturer Part Number: 0402N0R3B500CT
footprint CAP-0402 (0402 (1005M) Capacitor)
pins: 1, 2

## 0402N0R4C500CT
designator C?  Capacitance: 0.4pF  (hidden comment: *)
Capacitor, Ceramic (MLCC), 0.4pF, ±0.25pF, 50V, NP0, ±0.25pF, SMD 0402; Manufacturer: Walsin Tech Corp; Manufacturer Part Number: 0402N0R4C500CT
footprint CAP-0402 (0402 (1005M) Capacitor)
pins: 1, 2

## 0402N0R5A500CT
designator C?  Capacitance: 0.5pF  (hidden comment: *)
Capacitor, Ceramic (MLCC), 0.5pF, ±0.05pF, 50V, NP0, ±0.05pF, SMD 0402; Manufacturer: Walsin Tech Corp; Manufacturer Part Number: 0402N0R5A500CT
footprint CAP-0402 (0402 (1005M) Capacitor)
pins: 1, 2

## 0402N0R5B500CT
designator C?  Capacitance: 0.5pF  (hidden comment: *)
Capacitor, Ceramic (MLCC), 0.5pF, ±0.1pF, 50V, NP0, ±0.1pF, SMD 0402; Manufacturer: Walsin Tech Corp; Manufacturer Part Number: 0402N0R5B500CT
footprint CAP-0402 (0402 (1005M) Capacitor)
pins: 1, 2

## 0402N0R5C500CT
designator C?  Capacitance: 0.5pF  (hidden comment: *)
Capacitor, Ceramic (MLCC), 0.5pF, ±0.25pF, 50V, NP0, ±0.25pF, SMD 0402; Manufacturer: Walsin Tech Corp; Manufacturer Part Number: 0402N0R5C500CT
footprint CAP-0402 (0402 (1005M) Capacitor)
pins: 1, 2

## 0402N0R6B500CT
designator C?  Capacitance: 0.6pF  (hidden comment: *)
Capacitor, Ceramic (MLCC), 0.6pF, ±0.1pF, 50V, NP0, ±0.1pF, SMD 0402; Manufacturer: Walsin Tech Corp; Manufacturer Part Number: 0402N0R6B500CT
footprint CAP-0402 (0402 (1005M) Capacitor)
pins: 1, 2

## 0402N0R8B500CT
designator C?  Capacitance: 0.8pF  (hidden comment: *)
Capacitor, Ceramic (MLCC), 0.8pF, ±0.1pF, 50V, NP0, ±0.1pF, SMD 0402; Manufacturer: Walsin Tech Corp; Manufacturer Part Number: 0402N0R8B500CT
footprint CAP-0402 (0402 (1005M) Capacitor)
pins: 1, 2

## 0402N0R8C500CT
designator C?  Capacitance: 0.8pF  (hidden comment: *)
Capacitor, Ceramic (MLCC), 0.8pF, ±0.25pF, 50V, NP0, ±0.25pF, SMD 0402; Manufacturer: Walsin Tech Corp; Manufacturer Part Number: 0402N0R8C500CT
footprint CAP-0402 (0402 (1005M) Capacitor)
pins: 1, 2

## 0402N1R0B500CT
designator C?  Capacitance: 1pF  (hidden comment: *)
Capacitor, Ceramic (MLCC), 1pF, ±0.1pF, 50V, NP0, ±0.1pF, SMD 0402; Manufacturer: Walsin Tech Corp; Manufacturer Part Number: 0402N1R0B500CT
footprint CAP-0402 (0402 (1005M) Capacitor)
pins: 1, 2

## 0402N1R0C500CT
designator C?  Capacitance: 1pF  (hidden comment: *)
Capacitor, Ceramic (MLCC), 1pF, ±0.25pF, 50V, NP0, ±0.25pF, SMD 0402; Manufacturer: Walsin Tech Corp; Manufacturer Part Number: 0402N1R0C500CT
footprint CAP-0402 (0402 (1005M) Capacitor)
pins: 1, 2

## 0402N1R1C500CT
designator C?  Capacitance: 1.1pF  (hidden comment: *)
Capacitor, Ceramic (MLCC), 1.1pF, ±0.25pF, 50V, NP0, ±0.25pF, SMD 0402; Manufacturer: Walsin Tech Corp; Manufacturer Part Number: 0402N1R1C500CT
footprint CAP-0402 (0402 (1005M) Capacitor)
pins: 1, 2

## 0402N1R2A500CT
designator C?  Capacitance: 1.2pF  (hidden comment: *)
Capacitor, Ceramic (MLCC), 1.2pF, ±0.05pF, 50V, NP0, ±0.05pF, SMD 0402; Manufacturer: Walsin Tech Corp; Manufacturer Part Number: 0402N1R2A500CT
footprint CAP-0402 (0402 (1005M) Capacitor)
pins: 1, 2

## 0402N1R2B500CT
designator C?  Capacitance: 1.2pF  (hidden comment: *)
Capacitor, Ceramic (MLCC), 1.2pF, ±0.1pF, 50V, NP0, ±0.1pF, SMD 0402; Manufacturer: Walsin Tech Corp; Manufacturer Part Number: 0402N1R2B500CT
footprint CAP-0402 (0402 (1005M) Capacitor)
pins: 1, 2

## 0402N1R2C500CT
designator C?  Capacitance: 1.2pF  (hidden comment: *)
Capacitor, Ceramic (MLCC), 1.2pF, ±0.25pF, 50V, NP0, ±0.25pF, SMD 0402; Manufacturer: Walsin Tech Corp; Manufacturer Part Number: 0402N1R2C500CT
footprint CAP-0402 (0402 (1005M) Capacitor)
pins: 1, 2

## 0402N1R3C500CT
designator C?  Capacitance: 1.3pF  (hidden comment: *)
Capacitor, Ceramic (MLCC), 1.3pF, ±0.25pF, 50V, NP0, ±0.25pF, SMD 0402; Manufacturer: Walsin Tech Corp; Manufacturer Part Number: 0402N1R3C500CT
footprint CAP-0402 (0402 (1005M) Capacitor)
pins: 1, 2

## 0402N1R5B500CT
designator C?  Capacitance: 1.5pF  (hidden comment: *)
Capacitor, Ceramic (MLCC), 1.5pF, ±0.1pF, 50V, NP0, ±0.1pF, SMD 0402; Manufacturer: Walsin Tech Corp; Manufacturer Part Number: 0402N1R5B500CT
footprint CAP-0402 (0402 (1005M) Capacitor)
pins: 1, 2

## 0402N1R5C500CT
designator C?  Capacitance: 1.5pF  (hidden comment: *)
Capacitor, Ceramic (MLCC), 1.5pF, ±0.25pF, 50V, NP0, ±0.25pF, SMD 0402; Manufacturer: Walsin Tech Corp; Manufacturer Part Number: 0402N1R5C500CT
footprint CAP-0402 (0402 (1005M) Capacitor)
pins: 1, 2

## 0402N1R8A500CT
designator C?  Capacitance: 1.8pF  (hidden comment: *)
Capacitor, Ceramic (MLCC), 1.8pF, ±0.05pF, 50V, NP0, ±0.05pF, SMD 0402; Manufacturer: Walsin Tech Corp; Manufacturer Part Number: 0402N1R8A500CT
footprint CAP-0402 (0402 (1005M) Capacitor)
pins: 1, 2

## 0402N1R8B500CT
designator C?  Capacitance: 1.8pF  (hidden comment: *)
Capacitor, Ceramic (MLCC), 1.8pF, ±0.1pF, 50V, NP0, ±0.1pF, SMD 0402; Manufacturer: Walsin Tech Corp; Manufacturer Part Number: 0402N1R8B500CT
footprint CAP-0402 (0402 (1005M) Capacitor)
pins: 1, 2

## 0402N1R8C500CT
designator C?  Capacitance: 1.8pF  (hidden comment: *)
Capacitor, Ceramic (MLCC), 1.8pF, ±0.25pF, 50V, NP0, ±0.25pF, SMD 0402; Manufacturer: Walsin Tech Corp; Manufacturer Part Number: 0402N1R8C500CT
footprint CAP-0402 (0402 (1005M) Capacitor)
pins: 1, 2

## 0402N2R0A500CT
designator C?  Capacitance: 2pF  (hidden comment: *)
Capacitor, Ceramic (MLCC), 2pF, ±0.05pF, 50V, NP0, ±0.05pF, SMD 0402; Manufacturer: Walsin Tech Corp; Manufacturer Part Number: 0402N2R0A500CT
footprint CAP-0402 (0402 (1005M) Capacitor)
pins: 1, 2

## 0402N2R0B500CT
designator C?  Capacitance: 2pF  (hidden comment: *)
Capacitor, Ceramic (MLCC), 2pF, ±0.1pF, 50V, NP0, ±0.1pF, SMD 0402; Manufacturer: Walsin Tech Corp; Manufacturer Part Number: 0402N2R0B500CT
footprint CAP-0402 (0402 (1005M) Capacitor)
pins: 1, 2

## 0402N2R0C500CT
designator C?  Capacitance: 2pF  (hidden comment: *)
Capacitor, Ceramic (MLCC), 2pF, ±0.25pF, 50V, NP0, ±0.25pF, SMD 0402; Manufacturer: Walsin Tech Corp; Manufacturer Part Number: 0402N2R0C500CT
footprint CAP-0402 (0402 (1005M) Capacitor)
pins: 1, 2

## 0402N2R2C500CT
designator C?  Capacitance: 2.2pF  (hidden comment: *)
Capacitor, Ceramic (MLCC), 2.2pF, ±0.25pF, 50V, NP0, ±0.25pF, SMD 0402; Manufacturer: Walsin Tech Corp; Manufacturer Part Number: 0402N2R2C500CT
footprint CAP-0402 (0402 (1005M) Capacitor)
pins: 1, 2

## 0402N2R4B500CT
designator C?  Capacitance: 2.4pF  (hidden comment: *)
Capacitor, Ceramic (MLCC), 2.4pF, ±0.1pF, 50V, NP0, ±0.1pF, SMD 0402; Manufacturer: Walsin Tech Corp; Manufacturer Part Number: 0402N2R4B500CT
footprint CAP-0402 (0402 (1005M) Capacitor)
pins: 1, 2

## 0402N2R4C500CT
designator C?  Capacitance: 2.4pF  (hidden comment: *)
Capacitor, Ceramic (MLCC), 2.4pF, ±0.25pF, 50V, NP0, ±0.25pF, SMD 0402; Manufacturer: Walsin Tech Corp; Manufacturer Part Number: 0402N2R4C500CT
footprint CAP-0402 (0402 (1005M) Capacitor)
pins: 1, 2

## 0402N2R5B500CT
designator C?  Capacitance: 2.5pF  (hidden comment: *)
Capacitor, Ceramic (MLCC), 2.5pF, ±0.1pF, 50V, NP0, ±0.1pF, SMD 0402; Manufacturer: Walsin Tech Corp; Manufacturer Part Number: 0402N2R5B500CT
footprint CAP-0402 (0402 (1005M) Capacitor)
pins: 1, 2

## 0402N2R5C500CT
designator C?  Capacitance: 2.5pF  (hidden comment: *)
Capacitor, Ceramic (MLCC), 2.5pF, ±0.25pF, 50V, NP0, ±0.25pF, SMD 0402; Manufacturer: Walsin Tech Corp; Manufacturer Part Number: 0402N2R5C500CT
footprint CAP-0402 (0402 (1005M) Capacitor)
pins: 1, 2

## 0402N2R7B500CT
designator C?  Capacitance: 2.7pF  (hidden comment: *)
Capacitor, Ceramic (MLCC), 2.7pF, ±0.1pF, 50V, NP0, ±0.1pF, SMD 0402; Manufacturer: Walsin Tech Corp; Manufacturer Part Number: 0402N2R7B500CT
footprint CAP-0402 (0402 (1005M) Capacitor)
pins: 1, 2

## 0402N2R7C500CT
designator C?  Capacitance: 2.7pF  (hidden comment: *)
Capacitor, Ceramic (MLCC), 2.7pF, ±0.25pF, 50V, NP0, ±0.25pF, SMD 0402; Manufacturer: Walsin Tech Corp; Manufacturer Part Number: 0402N2R7C500CT
footprint CAP-0402 (0402 (1005M) Capacitor)
pins: 1, 2

## 0402N3R0B500CT
designator C?  Capacitance: 3pF  (hidden comment: *)
Capacitor, Ceramic (MLCC), 3pF, ±0.1pF, 50V, NP0, ±0.1pF, SMD 0402; Manufacturer: Walsin Tech Corp; Manufacturer Part Number: 0402N3R0B500CT
footprint CAP-0402 (0402 (1005M) Capacitor)
pins: 1, 2

## 0402N3R0C500CT
designator C?  Capacitance: 3pF  (hidden comment: *)
Capacitor, Ceramic (MLCC), 3pF, ±0.25pF, 50V, NP0, ±0.25pF, SMD 0402; Manufacturer: Walsin Tech Corp; Manufacturer Part Number: 0402N3R0C500CT
footprint CAP-0402 (0402 (1005M) Capacitor)
pins: 1, 2

## 0402N3R0D500CT
designator C?  Capacitance: 3pF  (hidden comment: *)
Capacitor, Ceramic (MLCC), 3pF, ±0.5pF, 50V, NP0, ±0.5pF, SMD 0402; Manufacturer: Walsin Tech Corp; Manufacturer Part Number: 0402N3R0D500CT
footprint CAP-0402 (0402 (1005M) Capacitor)
pins: 1, 2

## 0402N3R3B500CT
designator C?  Capacitance: 3.3pF  (hidden comment: *)
Capacitor, Ceramic (MLCC), 3.3pF, ±0.1pF, 50V, NP0, ±0.1pF, SMD 0402; Manufacturer: Walsin Tech Corp; Manufacturer Part Number: 0402N3R3B500CT
footprint CAP-0402 (0402 (1005M) Capacitor)
pins: 1, 2

## 0402N3R3C500CT
designator C?  Capacitance: 3.3pF  (hidden comment: *)
Capacitor, Ceramic (MLCC), 3.3pF, ±0.25pF, 50V, NP0, ±0.25pF, SMD 0402; Manufacturer: Walsin Tech Corp; Manufacturer Part Number: 0402N3R3C500CT
footprint CAP-0402 (0402 (1005M) Capacitor)
pins: 1, 2

## 0402N3R6B500
designator C?  Capacitance: 3.6pF  (hidden comment: *)
Capacitor, Ceramic (MLCC), 3.6pF, ±0.1pF, 50V, NP0, ±0.1pF, SMD 0402; Manufacturer: Walsin Tech Corp; Manufacturer Part Number: 0402N3R6B500
footprint CAP-0402 (0402 (1005M) Capacitor)
pins: 1, 2

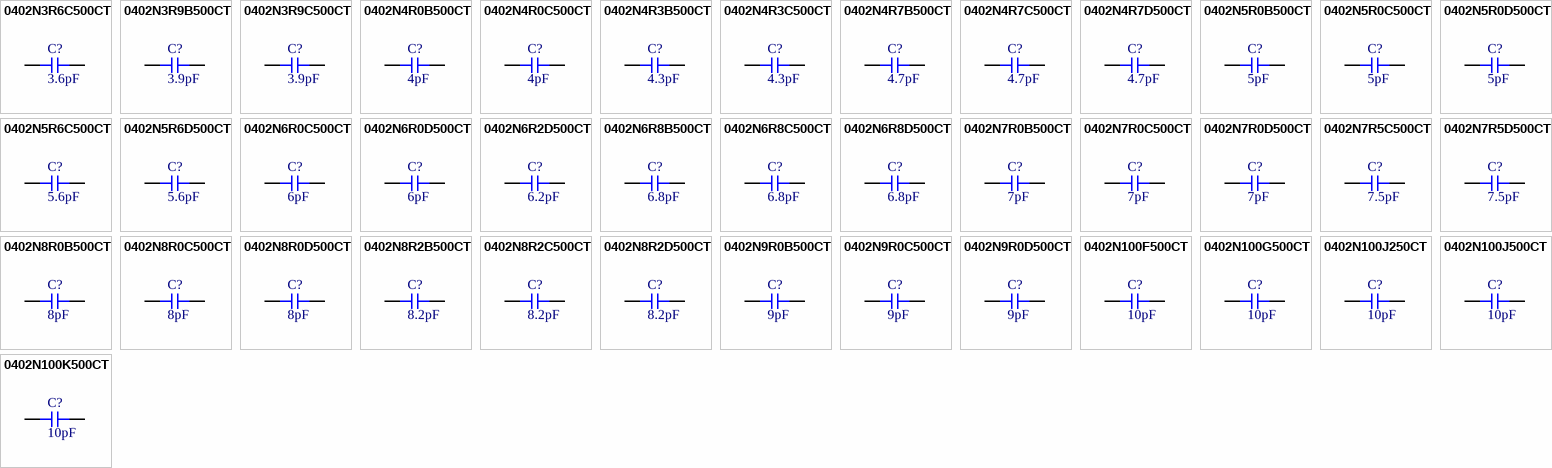
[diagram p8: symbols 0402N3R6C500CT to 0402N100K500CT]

## 0402N3R6C500CT
designator C?  Capacitance: 3.6pF  (hidden comment: *)
Capacitor, Ceramic (MLCC), 3.6pF, ±0.25pF, 50V, NP0, ±0.25pF, SMD 0402; Manufacturer: Walsin Tech Corp; Manufacturer Part Number: 0402N3R6C500CT
footprint CAP-0402 (0402 (1005M) Capacitor)
pins: 1, 2

## 0402N3R9B500CT
designator C?  Capacitance: 3.9pF  (hidden comment: *)
Capacitor, Ceramic (MLCC), 3.9pF, ±0.1pF, 50V, NP0, ±0.1pF, SMD 0402; Manufacturer: Walsin Tech Corp; Manufacturer Part Number: 0402N3R9B500CT
footprint CAP-0402 (0402 (1005M) Capacitor)
pins: 1, 2

## 0402N3R9C500CT
designator C?  Capacitance: 3.9pF  (hidden comment: *)
Capacitor, Ceramic (MLCC), 3.9pF, ±0.25pF, 50V, NP0, ±0.25pF, SMD 0402; Manufacturer: Walsin Tech Corp; Manufacturer Part Number: 0402N3R9C500CT
footprint CAP-0402 (0402 (1005M) Capacitor)
pins: 1, 2

## 0402N4R0B500CT
designator C?  Capacitance: 4pF  (hidden comment: *)
Capacitor, Ceramic (MLCC), 4pF, ±0.1pF, 50V, NP0, ±0.1pF, SMD 0402; Manufacturer: Walsin Tech Corp; Manufacturer Part Number: 0402N4R0B500CT
footprint CAP-0402 (0402 (1005M) Capacitor)
pins: 1, 2

## 0402N4R0C500CT
designator C?  Capacitance: 4pF  (hidden comment: *)
Capacitor, Ceramic (MLCC), 4pF, ±0.25pF, 50V, NP0, ±0.25pF, SMD 0402; Manufacturer: Walsin Tech Corp; Manufacturer Part Number: 0402N4R0C500CT
footprint CAP-0402 (0402 (1005M) Capacitor)
pins: 1, 2

## 0402N4R3B500CT
designator C?  Capacitance: 4.3pF  (hidden comment: *)
Capacitor, Ceramic (MLCC), 4.3pF, ±0.1pF, 50V, NP0, ±0.1pF, SMD 0402; Manufacturer: Walsin Tech Corp; Manufacturer Part Number: 0402N4R3B500CT
footprint CAP-0402 (0402 (1005M) Capacitor)
pins: 1, 2

## 0402N4R3C500CT
designator C?  Capacitance: 4.3pF  (hidden comment: *)
Capacitor, Ceramic (MLCC), 4.3pF, ±0.25pF, 50V, NP0, ±0.25pF, SMD 0402; Manufacturer: Walsin Tech Corp; Manufacturer Part Number: 0402N4R3C500CT
footprint CAP-0402 (0402 (1005M) Capacitor)
pins: 1, 2

## 0402N4R7B500CT
designator C?  Capacitance: 4.7pF  (hidden comment: *)
Capacitor, Ceramic (MLCC), 4.7pF, ±0.1pF, 50V, NP0, ±0.1pF, SMD 0402; Manufacturer: Walsin Tech Corp; Manufacturer Part Number: 0402N4R7B500CT
footprint CAP-0402 (0402 (1005M) Capacitor)
pins: 1, 2

## 0402N4R7C500CT
designator C?  Capacitance: 4.7pF  (hidden comment: *)
Capacitor, Ceramic (MLCC), 4.7pF, ±0.25pF, 50V, NP0, ±0.25pF, SMD 0402; Manufacturer: Walsin Tech Corp; Manufacturer Part Number: 0402N4R7C500CT
footprint CAP-0402 (0402 (1005M) Capacitor)
pins: 1, 2

## 0402N4R7D500CT
designator C?  Capacitance: 4.7pF  (hidden comment: *)
Capacitor, Ceramic (MLCC), 4.7pF, ±0.5pF, 50V, NP0, ±0.5pF, SMD 0402; Manufacturer: Walsin Tech Corp; Manufacturer Part Number: 0402N4R7D500CT
footprint CAP-0402 (0402 (1005M) Capacitor)
pins: 1, 2

## 0402N5R0B500CT
designator C?  Capacitance: 5pF  (hidden comment: *)
Capacitor, Ceramic (MLCC), 5pF, ±0.1pF, 50V, NP0, ±0.1pF, SMD 0402; Manufacturer: Walsin Tech Corp; Manufacturer Part Number: 0402N5R0B500CT
footprint CAP-0402 (0402 (1005M) Capacitor)
pins: 1, 2

## 0402N5R0C500CT
designator C?  Capacitance: 5pF  (hidden comment: *)
Capacitor, Ceramic (MLCC), 5pF, ±0.25pF, 50V, NP0, ±0.25pF, SMD 0402; Manufacturer: Walsin Tech Corp; Manufacturer Part Number: 0402N5R0C500CT
footprint CAP-0402 (0402 (1005M) Capacitor)
pins: 1, 2

## 0402N5R0D500CT
designator C?  Capacitance: 5pF  (hidden comment: *)
Capacitor, Ceramic (MLCC), 5pF, ±0.5pF, 50V, NP0, ±0.5pF, SMD 0402; Manufacturer: Walsin Tech Corp; Manufacturer Part Number: 0402N5R0D500CT
footprint CAP-0402 (0402 (1005M) Capacitor)
pins: 1, 2

## 0402N5R6C500CT
designator C?  Capacitance: 5.6pF  (hidden comment: *)
Capacitor, Ceramic (MLCC), 5.6pF, ±0.25pF, 50V, NP0, ±0.25pF, SMD 0402; Manufacturer: Walsin Tech Corp; Manufacturer Part Number: 0402N5R6C500CT
footprint CAP-0402 (0402 (1005M) Capacitor)
pins: 1, 2

## 0402N5R6D500CT
designator C?  Capacitance: 5.6pF  (hidden comment: *)
Capacitor, Ceramic (MLCC), 5.6pF, ±0.5pF, 50V, NP0, ±0.5pF, SMD 0402; Manufacturer: Walsin Tech Corp; Manufacturer Part Number: 0402N5R6D500CT
footprint CAP-0402 (0402 (1005M) Capacitor)
pins: 1, 2

## 0402N6R0C500CT
designator C?  Capacitance: 6pF  (hidden comment: *)
Capacitor, Ceramic (MLCC), 6pF, ±0.25pF, 50V, NP0, ±0.25pF, SMD 0402; Manufacturer: Walsin Tech Corp; Manufacturer Part Number: 0402N6R0C500CT
footprint CAP-0402 (0402 (1005M) Capacitor)
pins: 1, 2

## 0402N6R0D500CT
designator C?  Capacitance: 6pF  (hidden comment: *)
Capacitor, Ceramic (MLCC), 6pF, ±0.5pF, 50V, NP0, ±0.5pF, SMD 0402; Manufacturer: Walsin Tech Corp; Manufacturer Part Number: 0402N6R0D500CT
footprint CAP-0402 (0402 (1005M) Capacitor)
pins: 1, 2

## 0402N6R2D500CT
designator C?  Capacitance: 6.2pF  (hidden comment: *)
Capacitor, Ceramic (MLCC), 6.2pF, ±0.5pF, 50V, NP0, ±0.5pF, SMD 0402; Manufacturer: Walsin Tech Corp; Manufacturer Part Number: 0402N6R2D500CT
footprint CAP-0402 (0402 (1005M) Capacitor)
pins: 1, 2

## 0402N6R8B500CT
designator C?  Capacitance: 6.8pF  (hidden comment: *)
Capacitor, Ceramic (MLCC), 6.8pF, ±0.1pF, 50V, NP0, ±0.1pF, SMD 0402; Manufacturer: Walsin Tech Corp; Manufacturer Part Number: 0402N6R8B500CT
footprint CAP-0402 (0402 (1005M) Capacitor)
pins: 1, 2

## 0402N6R8C500CT
designator C?  Capacitance: 6.8pF  (hidden comment: *)
Capacitor, Ceramic (MLCC), 6.8pF, ±0.25pF, 50V, NP0, ±0.25pF, SMD 0402; Manufacturer: Walsin Tech Corp; Manufacturer Part Number: 0402N6R8C500CT
footprint CAP-0402 (0402 (1005M) Capacitor)
pins: 1, 2

## 0402N6R8D500CT
designator C?  Capacitance: 6.8pF  (hidden comment: *)
Capacitor, Ceramic (MLCC), 6.8pF, ±0.5pF, 50V, NP0, ±0.5pF, SMD 0402; Manufacturer: Walsin Tech Corp; Manufacturer Part Number: 0402N6R8D500CT
footprint CAP-0402 (0402 (1005M) Capacitor)
pins: 1, 2

## 0402N7R0B500CT
designator C?  Capacitance: 7pF  (hidden comment: *)
Capacitor, Ceramic (MLCC), 7pF, ±0.1pF, 50V, NP0, ±0.1pF, SMD 0402; Manufacturer: Walsin Tech Corp; Manufacturer Part Number: 0402N7R0B500CT
footprint CAP-0402 (0402 (1005M) Capacitor)
pins: 1, 2

## 0402N7R0C500CT
designator C?  Capacitance: 7pF  (hidden comment: *)
Capacitor, Ceramic (MLCC), 7pF, ±0.25pF, 50V, NP0, ±0.25pF, SMD 0402; Manufacturer: Walsin Tech Corp; Manufacturer Part Number: 0402N7R0C500CT
footprint CAP-0402 (0402 (1005M) Capacitor)
pins: 1, 2

## 0402N7R0D500CT
designator C?  Capacitance: 7pF  (hidden comment: *)
Capacitor, Ceramic (MLCC), 7pF, ±0.5pF, 50V, NP0, ±0.5pF, SMD 0402; Manufacturer: Walsin Tech Corp; Manufacturer Part Number: 0402N7R0D500CT
footprint CAP-0402 (0402 (1005M) Capacitor)
pins: 1, 2

## 0402N7R5C500CT
designator C?  Capacitance: 7.5pF  (hidden comment: *)
Capacitor, Ceramic (MLCC), 7.5pF, ±0.25pF, 50V, NP0, ±0.25pF, SMD 0402; Manufacturer: Walsin Tech Corp; Manufacturer Part Number: 0402N7R5C500CT
footprint CAP-0402 (0402 (1005M) Capacitor)
pins: 1, 2

## 0402N7R5D500CT
designator C?  Capacitance: 7.5pF  (hidden comment: *)
Capacitor, Ceramic (MLCC), 7.5pF, ±0.5pF, 50V, NP0, ±0.5pF, SMD 0402; Manufacturer: Walsin Tech Corp; Manufacturer Part Number: 0402N7R5D500CT
footprint CAP-0402 (0402 (1005M) Capacitor)
pins: 1, 2

## 0402N8R0B500CT
designator C?  Capacitance: 8pF  (hidden comment: *)
Capacitor, Ceramic (MLCC), 8pF, ±0.1pF, 50V, NP0, ±0.1pF, SMD 0402; Manufacturer: Walsin Tech Corp; Manufacturer Part Number: 0402N8R0B500CT
footprint CAP-0402 (0402 (1005M) Capacitor)
pins: 1, 2

## 0402N8R0C500CT
designator C?  Capacitance: 8pF  (hidden comment: *)
Capacitor, Ceramic (MLCC), 8pF, ±0.25pF, 50V, NP0, ±0.25pF, SMD 0402; Manufacturer: Walsin Tech Corp; Manufacturer Part Number: 0402N8R0C500CT
footprint CAP-0402 (0402 (1005M) Capacitor)
pins: 1, 2

## 0402N8R0D500CT
designator C?  Capacitance: 8pF  (hidden comment: *)
Capacitor, Ceramic (MLCC), 8pF, ±0.5pF, 50V, NP0, ±0.5pF, SMD 0402; Manufacturer: Walsin Tech Corp; Manufacturer Part Number: 0402N8R0D500CT
footprint CAP-0402 (0402 (1005M) Capacitor)
pins: 1, 2

## 0402N8R2B500CT
designator C?  Capacitance: 8.2pF  (hidden comment: *)
Capacitor, Ceramic (MLCC), 8.2pF, ±0.1pF, 50V, NP0, ±0.1pF, SMD 0402; Manufacturer: Walsin Tech Corp; Manufacturer Part Number: 0402N8R2B500CT
footprint CAP-0402 (0402 (1005M) Capacitor)
pins: 1, 2

## 0402N8R2C500CT
designator C?  Capacitance: 8.2pF  (hidden comment: *)
Capacitor, Ceramic (MLCC), 8.2pF, ±0.25pF, 50V, NP0, ±0.25pF, SMD 0402; Manufacturer: Walsin Tech Corp; Manufacturer Part Number: 0402N8R2C500CT
footprint CAP-0402 (0402 (1005M) Capacitor)
pins: 1, 2

## 0402N8R2D500CT
designator C?  Capacitance: 8.2pF  (hidden comment: *)
Capacitor, Ceramic (MLCC), 8.2pF, ±0.5pF, 50V, NP0, ±0.5pF, SMD 0402; Manufacturer: Walsin Tech Corp; Manufacturer Part Number: 0402N8R2D500CT
footprint CAP-0402 (0402 (1005M) Capacitor)
pins: 1, 2

## 0402N9R0B500CT
designator C?  Capacitance: 9pF  (hidden comment: *)
Capacitor, Ceramic (MLCC), 9pF, ±0.1pF, 50V, NP0, ±0.1pF, SMD 0402; Manufacturer: Walsin Tech Corp; Manufacturer Part Number: 0402N9R0B500CT
footprint CAP-0402 (0402 (1005M) Capacitor)
pins: 1, 2

## 0402N9R0C500CT
designator C?  Capacitance: 9pF  (hidden comment: *)
Capacitor, Ceramic (MLCC), 9pF, ±0.25pF, 50V, NP0, ±0.25pF, SMD 0402; Manufacturer: Walsin Tech Corp; Manufacturer Part Number: 0402N9R0C500CT
footprint CAP-0402 (0402 (1005M) Capacitor)
pins: 1, 2

## 0402N9R0D500CT
designator C?  Capacitance: 9pF  (hidden comment: *)
Capacitor, Ceramic (MLCC), 9pF, ±0.5pF, 50V, NP0, ±0.5pF, SMD 0402; Manufacturer: Walsin Tech Corp; Manufacturer Part Number: 0402N9R0D500CT
footprint CAP-0402 (0402 (1005M) Capacitor)
pins: 1, 2

## 0402N100F500CT
designator C?  Capacitance: 10pF  (hidden comment: *)
Capacitor, Ceramic (MLCC), 10pF, ±1%, 50V, NP0, ±1%, SMD 0402; Manufacturer: Walsin Tech Corp; Manufacturer Part Number: 0402N100F500CT
footprint CAP-0402 (0402 (1005M) Capacitor)
pins: 1, 2

## 0402N100G500CT
designator C?  Capacitance: 10pF  (hidden comment: *)
Capacitor, Ceramic (MLCC), 10pF, ±2%, 50V, NP0, ±2%, SMD 0402; Manufacturer: Walsin Tech Corp; Manufacturer Part Number: 0402N100G500CT
footprint CAP-0402 (0402 (1005M) Capacitor)
pins: 1, 2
